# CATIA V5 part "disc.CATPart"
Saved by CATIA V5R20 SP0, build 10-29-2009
Part number: disc
Bounding box of the stored display mesh (mm): x -82.595 to 2.595, y 53.138 to 69.637, z -42.627 to 42.627
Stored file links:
  C:\Users\joki\Desktop\Belleville spring\disc.CATPart
  Product2.CATProduct
  Product1.CATProduct
  C:\Users\joki\Desktop\Belleville spring\stred.CATPart
  C:\Users\joki\Desktop\Belleville spring\Assembly.CATProduct
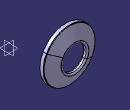
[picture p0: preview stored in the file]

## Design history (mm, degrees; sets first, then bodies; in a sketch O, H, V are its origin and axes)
Body1 (main body)
  Sketch1 on xy-plane, origin (0, 0, 0), H (1, 0, 0), V (0, 1, 0)
    point P1 (0.5622, 52.5412)
    point P2 (-82.6577, 52.5412)
    line L1 (-82.6577, 52.5412) -> (-60, 63.1067)
    point P3 (-60, 63.1067)
    line L2 (-82.6577, 60.2648) -> (-62.9583, 69.4508)
    axis line L3 (-40, 101.6308) -> (-40, -19.5253)
    line L4 (-62.9583, 69.4508) -> (-60, 70.8303)
    line L5 (-60, 63.1067) -> (-60, 70.8303)
    line L6 (-82.6577, 52.5412) -> (-82.6577, 60.2648)
    distance P1 P2 = 83.2199
    length L1 = 25
    distance L2 L1 = 7
    angle L1 H = 25
    distance V L3 = 40
    distance P3 L3 = 20
  Shaft1: profile Sketch1, axis Sketch1.L3, angle 360
  Fillet1: radius 2, on edge [face of Shaft1 from Sketch1.L5 | face of Shaft1 from Sketch1.L4]; edge [face of Shaft1 from Sketch1.L1 | face of Shaft1 from Sketch1.L5]
  Fillet2: radius 1, on edge [face of Shaft1 from Sketch1.L2 | face of Shaft1 from Sketch1.L6]; edge [face of Shaft1 from Sketch1.L6 | face of Shaft1 from Sketch1.L1]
